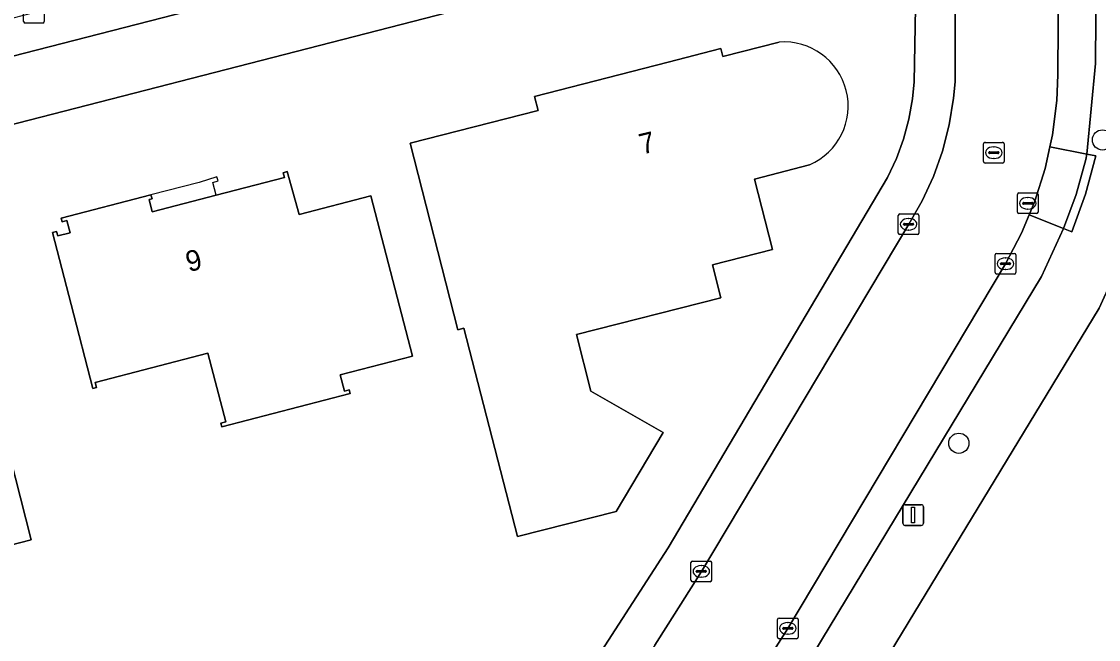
# Model space of a CAD drawing. Extents: x 158835 to 160077, y 386387 to 387778.
# Drawn here: x 159468.8 to 159520.8, y 386689.1 to 386719 of the extents above; entities that cross this region are included whole.
import ezdxf

# ---------------------------------------------------------------- set-up
doc = ezdxf.new("R2010")
doc.units = 0
for name, color, linetype in [('IMGEO_Boom', 7, 'Continuous'), ('IMGEO_Erf', 7, 'Continuous'), ('IMGEO_Kolk', 7, 'Continuous'), ('IMGEO_Lichtmast', 7, 'Continuous'), ('IMGEO_Pand', 7, 'Continuous'), ('IMGEO_Pand_nummerreeks', 7, 'Continuous'), ('IMGEO_Pand_overbouw', 7, 'Continuous'), ('IMGEO_Parkeervlak_open', 7, 'Continuous'), ('IMGEO_Rijbaan_lokaal_gesloten', 7, 'Continuous'), ('IMGEO_Rioolput', 7, 'Continuous'), ('IMGEO_Voetpad_open', 7, 'Continuous')]:
    doc.layers.add(name, color=color, linetype=linetype)

msp = doc.modelspace()

# ---------------------------------------------------------------- linework, layer by layer
at = {"layer": 'IMGEO_Boom'}
for centre in [(159520.987, 386713.228), (159514.05, 386698.566)]:
    msp.add_circle(centre, 0.489, dxfattribs=at)
at = {"layer": 'IMGEO_Erf'}
for points in [[(159500, 386722.142), (159452.288, 386709.846)], [(159523.936, 386720.207), (159523.989, 386717.606), (159523.81, 386715.012), (159523.4, 386712.444), (159522.762, 386709.923), (159521.901, 386707.468), (159520.825, 386705.101), (159506.854, 386682.053), (159500.252, 386671.907), (159500, 386671.529), (159492.426, 386660.371), (159492.025, 386659.896), (159480.297, 386643.692), (159466.865, 386626.712)], [(159487.016, 386673.557), (159487.077, 386673.647), (159489.757, 386677.629), (159489.836, 386677.746), (159499.829, 386693.238), (159500, 386693.513), (159510.606, 386711.419), (159511.034, 386712.323), (159511.379, 386713.262), (159511.639, 386714.228), (159511.811, 386715.214), (159511.887, 386716.039), (159511.952, 386719.617)], [(159487.54, 386713.069), (159493.724, 386714.655), (159493.557, 386715.329), (159500, 386716.992), (159502.548, 386717.65), (159502.648, 386717.262), (159505.369, 386717.958)], [(159506.842, 386712.025), (159504.174, 386711.333), (159505.041, 386707.931), (159502.142, 386707.192), (159502.549, 386705.593), (159495.577, 386703.817), (159496.269, 386701.084), (159499.767, 386699.087), (159497.488, 386695.274), (159492.734, 386694.053), (159490.144, 386704.126), (159489.853, 386704.051), (159487.54, 386713.069)]]:
    msp.add_lwpolyline(points, dxfattribs=at)
for points in [[(159477.777, 386702.913), (159472.332, 386701.502), (159472.394, 386701.26), (159472.21, 386701.212), (159471.165, 386705.272), (159470.271, 386708.76), (159470.467, 386708.808), (159470.522, 386708.585), (159471.116, 386708.74), (159470.954, 386709.327), (159470.732, 386709.268), (159470.683, 386709.452), (159475.024, 386710.572), (159475.074, 386710.388), (159474.939, 386710.352), (159475.079, 386709.747), (159478.177, 386710.553), (159481.475, 386711.412), (159481.412, 386711.644), (159481.6, 386711.696), (159482.181, 386709.616), (159485.637, 386710.52), (159487.661, 386702.78), (159484.167, 386701.875), (159484.37, 386701.089), (159484.603, 386701.149), (159484.651, 386700.965), (159478.449, 386699.358), (159478.401, 386699.543), (159478.634, 386699.603)], [(159449.94, 386698.562), (159448.814, 386702.925), (159449.976, 386703.243), (159449.754, 386704.104), (159454.605, 386705.345), (159454.828, 386704.474), (159457.463, 386705.146), (159461.901, 386706.279), (159463.016, 386701.909), (159466.929, 386702.912), (159469.231, 386693.903), (159465.029, 386692.822), (159464.282, 386695.727), (159459.829, 386694.582), (159459.777, 386694.785), (159452.99, 386693.04), (159452.291, 386695.76), (159451.91, 386695.676), (159451.102, 386698.862)]]:
    msp.add_lwpolyline(points, close=True, dxfattribs=at)
msp.add_arc((159505.603, 386714.867), 3.1, 293.5507, 94.3354, dxfattribs=at)
at = {"layer": 'IMGEO_Kolk'}
for p, q in [((159468.868, 386718.952), (159468.868, 386719.804)), ((159469.869, 386719.804), (159469.869, 386718.952)), ((159469.795, 386718.878), (159468.943, 386718.878)), ((159511.123, 386708.725), (159511.123, 386709.577)), ((159511.198, 386709.651), (159512.05, 386709.651)), ((159511.611, 386709.431), (159511.636, 386709.431)), ((159512.124, 386709.577), (159512.124, 386708.725)), ((159511.382, 386709.145), (159511.382, 386709.157)), ((159511.82, 386709.108), (159511.422, 386709.108)), ((159511.425, 386709.194), (159511.823, 386709.194)), ((159511.634, 386708.871), (159511.609, 386708.871)), ((159511.866, 386709.157), (159511.866, 386709.145)), ((159512.05, 386708.651), (159511.198, 386708.651)), ((159515.803, 386706.819), (159515.803, 386707.671)), ((159515.878, 386707.745), (159516.73, 386707.745)), ((159516.105, 386707.288), (159516.503, 386707.288)), ((159516.291, 386707.525), (159516.316, 386707.525)), ((159516.804, 386707.671), (159516.804, 386706.819)), ((159516.062, 386707.239), (159516.062, 386707.251)), ((159516.5, 386707.202), (159516.102, 386707.202)), ((159516.314, 386706.965), (159516.289, 386706.965)), ((159516.546, 386707.251), (159516.546, 386707.239)), ((159516.73, 386706.745), (159515.878, 386706.745)), ((159501.108, 386691.946), (159501.108, 386692.798)), ((159501.183, 386692.872), (159502.035, 386692.872)), ((159502.109, 386692.798), (159502.109, 386691.946)), ((159501.367, 386692.366), (159501.367, 386692.378)), ((159501.805, 386692.329), (159501.407, 386692.329)), ((159501.41, 386692.415), (159501.808, 386692.415)), ((159501.596, 386692.652), (159501.621, 386692.652)), ((159501.851, 386692.378), (159501.851, 386692.366)), ((159502.035, 386691.872), (159501.183, 386691.872)), ((159501.619, 386692.092), (159501.594, 386692.092)), ((159505.362, 386690.118), (159506.214, 386690.118)), ((159505.287, 386689.192), (159505.287, 386690.044)), ((159505.546, 386689.612), (159505.546, 386689.624)), ((159505.589, 386689.661), (159505.987, 386689.661)), ((159505.775, 386689.898), (159505.8, 386689.898)), ((159506.03, 386689.624), (159506.03, 386689.612)), ((159506.288, 386690.044), (159506.288, 386689.192)), ((159506.214, 386689.118), (159505.362, 386689.118)), ((159505.984, 386689.575), (159505.586, 386689.575)), ((159505.798, 386689.338), (159505.773, 386689.338))]:
    msp.add_line(p, q, dxfattribs=at)
for points in [[(159468.868, 386718.952), (159468.868, 386719.804)], [(159469.869, 386719.804), (159469.869, 386718.952)], [(159469.795, 386718.878), (159468.943, 386718.878)], [(159511.123, 386708.725), (159511.123, 386709.577)], [(159511.198, 386709.651), (159512.05, 386709.651)], [(159512.124, 386709.577), (159512.124, 386708.725)], [(159512.05, 386708.651), (159511.198, 386708.651)], [(159515.803, 386706.819), (159515.803, 386707.671)], [(159515.878, 386707.745), (159516.73, 386707.745)], [(159516.804, 386707.671), (159516.804, 386706.819)], [(159516.73, 386706.745), (159515.878, 386706.745)], [(159501.108, 386691.946), (159501.108, 386692.798)], [(159501.183, 386692.872), (159502.035, 386692.872)], [(159502.109, 386692.798), (159502.109, 386691.946)], [(159502.035, 386691.872), (159501.183, 386691.872)], [(159505.362, 386690.118), (159506.214, 386690.118)], [(159505.287, 386689.192), (159505.287, 386690.044)], [(159506.288, 386690.044), (159506.288, 386689.192)], [(159506.214, 386689.118), (159505.362, 386689.118)]]:
    msp.add_lwpolyline(points, dxfattribs=at)
for centre, radius, start, end in [((159468.945, 386718.954), 0.0765, 181.552, 268.448), ((159468.945, 386718.954), 0.0765, 181.552, 268.448), ((159469.793, 386718.954), 0.0765, 271.552, 358.448), ((159469.793, 386718.954), 0.0765, 271.552, 358.448), ((159511.2, 386709.575), 0.0765, 91.552, 178.448), ((159511.2, 386709.575), 0.0765, 91.552, 178.448), ((159512.048, 386709.575), 0.0765, 1.552, 88.448), ((159512.048, 386709.575), 0.0765, 1.552, 88.448), ((159511.422, 386709.154), 0.0403, 85.8775, 175.7526), ((159511.419, 386709.144), 0.0366, 178.938, 274.7102), ((159511.823, 386709.151), 0.043, 264.8664, 352.4533), ((159511.827, 386709.156), 0.0386, 1.7309, 96.639), ((159511.2, 386708.727), 0.0765, 181.552, 268.448), ((159511.2, 386708.727), 0.0765, 181.552, 268.448), ((159512.048, 386708.727), 0.0765, 271.552, 358.448), ((159512.048, 386708.727), 0.0765, 271.552, 358.448), ((159515.88, 386707.669), 0.0765, 91.552, 178.448), ((159515.88, 386707.669), 0.0765, 91.552, 178.448), ((159516.102, 386707.248), 0.0403, 85.8775, 175.7526), ((159516.507, 386707.25), 0.0386, 1.7309, 96.639), ((159516.728, 386707.669), 0.0765, 1.552, 88.448), ((159516.728, 386707.669), 0.0765, 1.552, 88.448), ((159515.88, 386706.821), 0.0765, 181.552, 268.448), ((159515.88, 386706.821), 0.0765, 181.552, 268.448), ((159516.099, 386707.238), 0.0366, 178.938, 274.7102), ((159516.503, 386707.245), 0.043, 264.8664, 352.4533), ((159516.728, 386706.821), 0.0765, 271.552, 358.448), ((159516.728, 386706.821), 0.0765, 271.552, 358.448), ((159501.185, 386692.796), 0.0765, 91.552, 178.448), ((159501.185, 386692.796), 0.0765, 91.552, 178.448), ((159502.033, 386692.796), 0.0765, 1.552, 88.448), ((159502.033, 386692.796), 0.0765, 1.552, 88.448), ((159501.407, 386692.375), 0.0403, 85.8775, 175.7526), ((159501.404, 386692.365), 0.0366, 178.938, 274.7102), ((159501.808, 386692.372), 0.043, 264.8664, 352.4533), ((159501.812, 386692.377), 0.0386, 1.7309, 96.639), ((159501.185, 386691.948), 0.0765, 181.552, 268.448), ((159501.185, 386691.948), 0.0765, 181.552, 268.448), ((159502.033, 386691.948), 0.0765, 271.552, 358.448), ((159502.033, 386691.948), 0.0765, 271.552, 358.448), ((159505.364, 386690.042), 0.0765, 91.552, 178.448), ((159505.364, 386690.042), 0.0765, 91.552, 178.448), ((159506.212, 386690.042), 0.0765, 1.552, 88.448), ((159506.212, 386690.042), 0.0765, 1.552, 88.448), ((159505.586, 386689.621), 0.0403, 85.8775, 175.7526), ((159505.583, 386689.611), 0.0366, 178.938, 274.7102), ((159505.987, 386689.618), 0.043, 264.8664, 352.4533), ((159505.991, 386689.623), 0.0386, 1.7309, 96.639), ((159505.364, 386689.194), 0.0765, 181.552, 268.448), ((159505.364, 386689.194), 0.0765, 181.552, 268.448), ((159506.212, 386689.194), 0.0765, 271.552, 358.448), ((159506.212, 386689.194), 0.0765, 271.552, 358.448)]:
    msp.add_arc(centre, radius, start, end, dxfattribs=at)
for centre, major_axis, ratio, start_param, end_param in [((159511.61, 386709.151), (-0.387, 0.002), 0.722429, 4.712389, 7.853982), ((159511.635, 386709.151), (-0.39, 0.002), 0.717154, 1.570796, 4.712389), ((159516.29, 386707.245), (-0.387, 0.002), 0.722429, 4.712389, 7.853982), ((159516.315, 386707.245), (-0.39, 0.002), 0.717154, 1.570796, 4.712389), ((159501.595, 386692.372), (-0.387, 0.002), 0.722429, 4.712389, 7.853982), ((159501.62, 386692.372), (-0.39, 0.002), 0.717154, 1.570796, 4.712389), ((159505.774, 386689.618), (-0.387, 0.002), 0.722429, 4.712389, 7.853982), ((159505.799, 386689.618), (-0.39, 0.002), 0.717154, 1.570796, 4.712389)]:
    msp.add_ellipse(centre, major_axis=major_axis, ratio=ratio, start_param=start_param, end_param=end_param, dxfattribs=at)
at = {"layer": 'IMGEO_Lichtmast'}
for p, q in [((159511.345, 386694.696), (159511.345, 386695.496)), ((159511.345, 386695.496), (159511.345, 386694.696)), ((159511.445, 386695.596), (159512.235, 386695.596)), ((159512.235, 386695.596), (159511.445, 386695.596)), ((159512.335, 386695.496), (159512.335, 386694.696)), ((159512.335, 386694.696), (159512.335, 386695.496)), ((159512.235, 386694.596), (159511.445, 386694.596)), ((159511.445, 386694.596), (159512.235, 386694.596))]:
    msp.add_line(p, q, dxfattribs=at)
msp.add_lwpolyline([(159511.765, 386695.471), (159511.915, 386695.471), (159511.915, 386694.721), (159511.765, 386694.721), (159511.765, 386695.471)], dxfattribs=at)
for centre, start, end in [((159511.445, 386695.496), 90, 180), ((159511.445, 386695.496), 90, 180), ((159512.235, 386695.496), 0, 90), ((159512.235, 386695.496), 360, 90), ((159511.445, 386694.696), 180, 270), ((159511.445, 386694.696), 180, 270), ((159512.235, 386694.696), 270, 0), ((159512.235, 386694.696), 270, 0)]:
    msp.add_arc(centre, 0.1, start, end, dxfattribs=at)
at = {"layer": 'IMGEO_Pand'}
msp.add_lwpolyline([(159505.369, 386717.958), (159502.648, 386717.262), (159502.548, 386717.65), (159500, 386716.992), (159493.557, 386715.329), (159493.724, 386714.655), (159487.54, 386713.069), (159489.853, 386704.051), (159490.144, 386704.126), (159492.734, 386694.053), (159497.488, 386695.274), (159499.767, 386699.087), (159496.269, 386701.084), (159495.577, 386703.817), (159502.549, 386705.593), (159502.142, 386707.192), (159505.041, 386707.931), (159504.174, 386711.333), (159506.842, 386712.025)], dxfattribs=at)
for points in [[(159470.683, 386709.452), (159470.732, 386709.268), (159470.954, 386709.327), (159471.116, 386708.74), (159470.522, 386708.585), (159470.467, 386708.808), (159470.271, 386708.76), (159471.165, 386705.272), (159472.21, 386701.212), (159472.394, 386701.26), (159472.332, 386701.502), (159477.777, 386702.913), (159478.634, 386699.603), (159478.401, 386699.543), (159478.449, 386699.358), (159484.651, 386700.965), (159484.603, 386701.149), (159484.37, 386701.089), (159484.167, 386701.875), (159487.661, 386702.78), (159485.637, 386710.52), (159482.181, 386709.616), (159481.6, 386711.696), (159481.412, 386711.644), (159481.475, 386711.412), (159478.177, 386710.553), (159475.079, 386709.747), (159474.939, 386710.352), (159475.074, 386710.388), (159475.024, 386710.572)], [(159457.463, 386705.146), (159454.828, 386704.474), (159454.605, 386705.345), (159449.754, 386704.104), (159449.976, 386703.243), (159448.814, 386702.925), (159449.94, 386698.562), (159451.102, 386698.862), (159451.91, 386695.676), (159452.291, 386695.76), (159452.99, 386693.04), (159459.777, 386694.785), (159459.829, 386694.582), (159464.282, 386695.727), (159465.029, 386692.822), (159469.231, 386693.903), (159466.929, 386702.912), (159463.016, 386701.909), (159461.901, 386706.279)]]:
    msp.add_lwpolyline(points, close=True, dxfattribs=at)
msp.add_arc((159505.603, 386714.867), 3.1, 293.5507, 94.3354, dxfattribs=at)
at = {"layer": 'IMGEO_Pand_overbouw'}
msp.add_lwpolyline([(159475.024, 386710.572), (159475.074, 386710.388), (159474.939, 386710.352), (159475.079, 386709.747), (159478.177, 386710.553), (159478.018, 386711.176), (159478.262, 386711.251), (159478.206, 386711.437), (159477.358, 386711.178)], close=True, dxfattribs=at)
at = {"layer": 'IMGEO_Parkeervlak_open'}
for points in [[(159478.768, 386721.793), (159469.368, 386719.379), (159462.852, 386717.704), (159463.303, 386715.988), (159463.438, 386716.024), (159479.208, 386720.08)], [(159518.046, 386706.634), (159519.101, 386708.953), (159517.443, 386709.606), (159517.076, 386708.722), (159516.302, 386707.245), (159505.787, 386689.619), (159502.694, 386684.743), (159504.222, 386683.773), (159504.259, 386683.831)]]:
    msp.add_lwpolyline(points, close=True, dxfattribs=at)
msp.add_lwpolyline([(159518.864, 386721.239), (159518.834, 386716.37), (159518.776, 386715.135), (159518.568, 386713.481), (159518.439, 386712.887), (159520.24, 386712.542), (159520.658, 386716.928), (159520.682, 386721.334)], dxfattribs=at)
at = {"layer": 'IMGEO_Rijbaan_lokaal_gesloten'}
for points in [[(159513.878, 386721.278), (159513.869, 386716.038), (159513.796, 386715.241), (159513.584, 386713.955), (159513.258, 386712.692), (159512.821, 386711.465), (159512.275, 386710.281), (159511.626, 386709.15), (159501.61, 386692.371), (159500.806, 386691.095), (159500, 386689.822), (159499.36, 386688.811), (159497.335, 386685.65), (159492.103, 386677.614), (159491.469, 386676.644), (159491.393, 386676.531), (159488.703, 386672.537), (159488.647, 386672.459), (159474.87, 386653.114), (159472.629, 386650.095), (159472.496, 386649.912), (159463.597, 386638.445)], [(159465.699, 386633.096), (159473.919, 386643.589), (159475.879, 386646.09), (159476.255, 386646.598), (159484.227, 386657.37), (159484.364, 386657.566), (159486.494, 386660.609), (159488.253, 386663.123), (159495.988, 386674.563), (159498.178, 386677.802), (159500, 386680.496), (159500.64, 386681.505), (159502.694, 386684.743), (159505.787, 386689.619), (159516.302, 386707.245), (159517.076, 386708.722), (159517.443, 386709.606), (159517.715, 386710.261), (159518.213, 386711.852), (159518.439, 386712.887), (159518.568, 386713.481), (159518.776, 386715.135), (159518.834, 386716.37), (159518.864, 386721.239)]]:
    msp.add_lwpolyline(points, dxfattribs=at)
at = {"layer": 'IMGEO_Rioolput'}
for p, q in [((159515.239, 386712.186), (159515.239, 386713.038)), ((159515.314, 386713.112), (159516.166, 386713.112)), ((159516.24, 386713.038), (159516.24, 386712.186)), ((159515.498, 386712.606), (159515.498, 386712.618)), ((159515.936, 386712.569), (159515.538, 386712.569)), ((159515.541, 386712.655), (159515.939, 386712.655)), ((159515.727, 386712.892), (159515.752, 386712.892)), ((159515.982, 386712.618), (159515.982, 386712.606)), ((159516.166, 386712.112), (159515.314, 386712.112)), ((159515.75, 386712.332), (159515.725, 386712.332)), ((159516.877, 386709.739), (159516.877, 386710.591)), ((159516.952, 386710.665), (159517.804, 386710.665)), ((159517.365, 386710.445), (159517.39, 386710.445)), ((159517.878, 386710.591), (159517.878, 386709.739)), ((159517.136, 386710.159), (159517.136, 386710.171)), ((159517.574, 386710.122), (159517.176, 386710.122)), ((159517.179, 386710.208), (159517.577, 386710.208)), ((159517.388, 386709.885), (159517.363, 386709.885)), ((159517.62, 386710.171), (159517.62, 386710.159)), ((159517.804, 386709.665), (159516.952, 386709.665))]:
    msp.add_line(p, q, dxfattribs=at)
for points in [[(159515.239, 386712.186), (159515.239, 386713.038)], [(159515.314, 386713.112), (159516.166, 386713.112)], [(159516.24, 386713.038), (159516.24, 386712.186)], [(159516.166, 386712.112), (159515.314, 386712.112)], [(159516.877, 386709.739), (159516.877, 386710.591)], [(159516.952, 386710.665), (159517.804, 386710.665)], [(159517.878, 386710.591), (159517.878, 386709.739)], [(159517.804, 386709.665), (159516.952, 386709.665)]]:
    msp.add_lwpolyline(points, dxfattribs=at)
for centre, radius, start, end in [((159515.316, 386713.036), 0.0765, 91.552, 178.448), ((159515.316, 386713.036), 0.0765, 91.552, 178.448), ((159516.164, 386713.036), 0.0765, 1.552, 88.448), ((159516.164, 386713.036), 0.0765, 1.552, 88.448), ((159515.538, 386712.615), 0.0403, 85.8775, 175.7526), ((159515.535, 386712.605), 0.0366, 178.938, 274.7102), ((159515.939, 386712.612), 0.043, 264.8664, 352.4533), ((159515.943, 386712.617), 0.0386, 1.7309, 96.639), ((159515.316, 386712.188), 0.0765, 181.552, 268.448), ((159515.316, 386712.188), 0.0765, 181.552, 268.448), ((159516.164, 386712.188), 0.0765, 271.552, 358.448), ((159516.164, 386712.188), 0.0765, 271.552, 358.448), ((159516.954, 386710.589), 0.0765, 91.552, 178.448), ((159516.954, 386710.589), 0.0765, 91.552, 178.448), ((159517.802, 386710.589), 0.0765, 1.552, 88.448), ((159517.802, 386710.589), 0.0765, 1.552, 88.448), ((159517.176, 386710.168), 0.0403, 85.8775, 175.7526), ((159517.173, 386710.158), 0.0366, 178.938, 274.7102), ((159517.577, 386710.165), 0.043, 264.8664, 352.4533), ((159517.581, 386710.17), 0.0386, 1.7309, 96.639), ((159516.954, 386709.741), 0.0765, 181.552, 268.448), ((159516.954, 386709.741), 0.0765, 181.552, 268.448), ((159517.802, 386709.741), 0.0765, 271.552, 358.448), ((159517.802, 386709.741), 0.0765, 271.552, 358.448)]:
    msp.add_arc(centre, radius, start, end, dxfattribs=at)
for centre, major_axis, ratio, start_param, end_param in [((159515.726, 386712.612), (-0.387, 0.002), 0.722429, 4.712389, 7.853982), ((159515.751, 386712.612), (-0.39, 0.002), 0.717154, 1.570796, 4.712389), ((159517.364, 386710.165), (-0.387, 0.002), 0.722429, 4.712389, 7.853982), ((159517.389, 386710.165), (-0.39, 0.002), 0.717154, 1.570796, 4.712389)]:
    msp.add_ellipse(centre, major_axis=major_axis, ratio=ratio, start_param=start_param, end_param=end_param, dxfattribs=at)
at = {"layer": 'IMGEO_Voetpad_open'}
for points in [[(159452.919, 386610.024), (159466.865, 386626.712), (159480.297, 386643.692), (159492.025, 386659.896), (159492.426, 386660.371), (159500, 386671.529), (159500.252, 386671.907), (159506.854, 386682.053), (159520.825, 386705.101), (159521.901, 386707.468), (159522.762, 386709.923), (159523.4, 386712.444), (159523.81, 386715.012), (159523.989, 386717.606), (159523.936, 386720.207), (159523.829, 386721.437), (159523.607, 386726.844), (159524.846, 386728.532), (159523.605, 386733.299), (159523.378, 386733.241)], [(159452.288, 386709.846), (159500, 386722.142)], [(159520.682, 386721.334), (159520.658, 386716.928), (159520.24, 386712.542), (159520.663, 386712.461), (159520.172, 386710.6), (159519.507, 386708.793), (159519.101, 386708.953), (159518.046, 386706.634), (159504.259, 386683.831)], [(159499.36, 386688.811), (159500, 386689.822), (159500.806, 386691.095), (159501.61, 386692.371), (159511.626, 386709.15), (159512.275, 386710.281), (159512.821, 386711.465), (159513.258, 386712.692), (159513.584, 386713.955), (159513.796, 386715.241), (159513.869, 386716.038), (159513.878, 386721.278)], [(159479.208, 386720.08), (159463.438, 386716.024)], [(159511.952, 386719.617), (159511.887, 386716.039), (159511.811, 386715.214), (159511.639, 386714.228), (159511.379, 386713.262), (159511.034, 386712.323), (159510.606, 386711.419), (159500, 386693.513), (159499.829, 386693.238), (159489.836, 386677.746)]]:
    msp.add_lwpolyline(points, dxfattribs=at)
for points in [[(159520.182, 386712.278), (159520.24, 386712.542), (159518.439, 386712.887), (159518.213, 386711.852), (159517.715, 386710.261), (159517.443, 386709.606), (159519.101, 386708.953), (159519.716, 386710.592)], [(159520.24, 386712.542), (159520.182, 386712.278), (159519.716, 386710.592), (159519.101, 386708.953), (159519.507, 386708.793), (159520.172, 386710.6), (159520.663, 386712.461)]]:
    msp.add_lwpolyline(points, close=True, dxfattribs=at)

# ---------------------------------------------------------------- texts
at = {"layer": 'IMGEO_Pand_nummerreeks'}
for s, rotation, p in [('7', 13.814, (159498.744, 386712.512)), ('9', 14.4636, (159476.848, 386706.831))]:
    msp.add_text(s, height=1, rotation=rotation, dxfattribs=at).set_placement(p)

doc.saveas('drawing.dxf')
